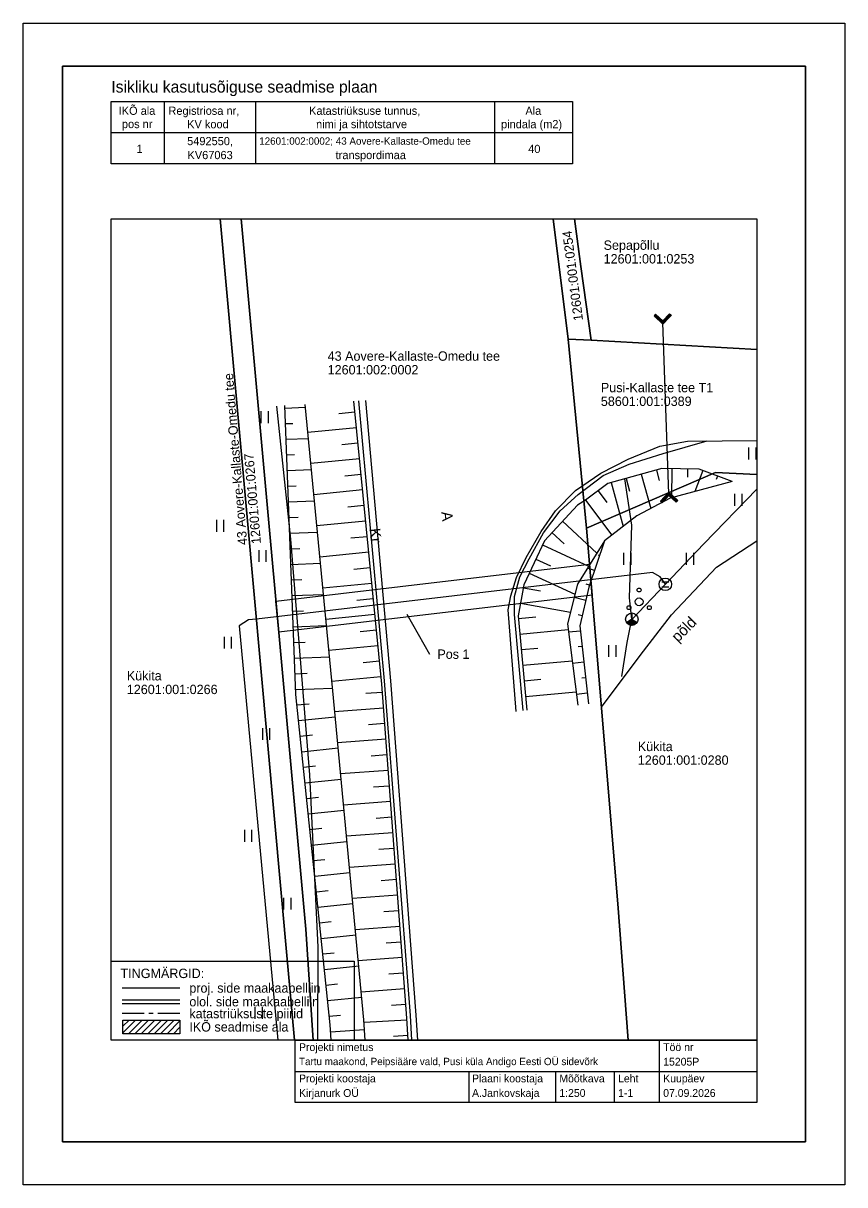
# Model space of a CAD drawing. Extents: x 683366.9 to 683419.4, y 6504541.6 to 6504615.8.
import ezdxf

# ---------------------------------------------------------------- set-up
doc = ezdxf.new("R2010")
doc.units = 0
for name, color, linetype in [('HALJASTUS', 7, 'Continuous'), ('KASUTUSALA', 7, 'Continuous'), ('PIIR', 7, 'Continuous'), ('PR_SIDE', 7, 'Continuous'), ('PUU', 7, 'Continuous'), ('RELJEEF', 7, 'Continuous'), ('SIKAEV', 7, 'Continuous'), ('SITRASS', 7, 'Continuous'), ('TEE', 7, 'Continuous'), ('TRUUP', 7, 'Continuous'), ('VORMISTUS', 7, 'Continuous')]:
    doc.layers.add(name, color=color, linetype=linetype)

msp = doc.modelspace()

# ---------------------------------------------------------------- linework, layer by layer
at = {"layer": 'HALJASTUS'}
for p, q in [((683382.127, 6504591.003), (683382.127, 6504590.242)), ((683382.583, 6504591.003), (683382.583, 6504590.242)), ((683413.292, 6504588.688), (683413.292, 6504587.927)), ((683413.747, 6504588.688), (683413.747, 6504587.927)), ((683412.397, 6504585.715), (683412.397, 6504584.954)), ((683412.852, 6504585.715), (683412.852, 6504584.954)), ((683379.285, 6504584.061), (683379.285, 6504583.3)), ((683379.74, 6504584.061), (683379.74, 6504583.3)), ((683381.983, 6504582.132), (683381.983, 6504581.371)), ((683382.438, 6504582.132), (683382.438, 6504581.371)), ((683405.305, 6504581.949), (683405.305, 6504581.188)), ((683405.76, 6504581.949), (683405.76, 6504581.188)), ((683409.309, 6504581.949), (683409.309, 6504581.188)), ((683409.764, 6504581.949), (683409.764, 6504581.188)), ((683379.767, 6504576.588), (683379.767, 6504575.827)), ((683380.222, 6504576.588), (683380.222, 6504575.827)), ((683404.34, 6504576.059), (683404.34, 6504575.298)), ((683404.795, 6504576.059), (683404.795, 6504575.298)), ((683382.224, 6504570.755), (683382.224, 6504569.993)), ((683382.679, 6504570.755), (683382.679, 6504569.993)), ((683381.068, 6504564.246), (683381.068, 6504563.485)), ((683381.523, 6504564.246), (683381.523, 6504563.485)), ((683383.573, 6504559.907), (683383.573, 6504559.146)), ((683384.028, 6504559.907), (683384.028, 6504559.146)), ((683381.742, 6504552.916), (683381.742, 6504552.155)), ((683382.197, 6504552.916), (683382.197, 6504552.155))]:
    msp.add_line(p, q, dxfattribs=at)
msp.add_lwpolyline([(683403.882, 6504572.085), (683406.35, 6504575.392), (683408.363, 6504577.994), (683411.241, 6504581.038), (683413.81, 6504582.721)], dxfattribs=at)
at = {"layer": 'KASUTUSALA'}
msp.add_lwpolyline([(683403.121, 6504581.232), (683403.287, 6504579.238), (683383.264, 6504576.881), (683383.083, 6504578.873)], close=True, dxfattribs=at)
at = {"layer": 'PIIR'}
for p, q in [((683384.272, 6504550.807), (683379.529, 6504603.307)), ((683379.529, 6504603.307), (683384.272, 6504550.807))]:
    msp.add_line(p, q, dxfattribs=at)
for points in [[(683385.461, 6504550.807), (683384.99, 6504557.89), (683380.863, 6504603.307)], [(683380.863, 6504603.307), (683384.99, 6504557.89), (683385.461, 6504550.807)], [(683400.81, 6504603.307), (683401.76, 6504595.62), (683403.22, 6504595.54), (683402.57, 6504600.25), (683402.154, 6504603.307)], [(683405.591, 6504550.807), (683404.93, 6504559.51), (683402.93, 6504583.52), (683401.76, 6504595.62), (683400.81, 6504603.307)], [(683402.154, 6504603.307), (683402.57, 6504600.25), (683403.22, 6504595.54), (683413.81, 6504594.943)], [(683413.81, 6504594.943), (683403.22, 6504595.54), (683401.76, 6504595.62), (683402.93, 6504583.52), (683411.18, 6504587.08), (683413.81, 6504586.956)], [(683413.81, 6504586.956), (683411.18, 6504587.08), (683402.93, 6504583.52), (683404.93, 6504559.51), (683405.591, 6504550.807)]]:
    msp.add_lwpolyline(points, dxfattribs=at)
at = {"layer": 'PR_SIDE'}
for p, q in [((683405.828, 6504577.696), (683407.97, 6504579.943)), ((683407.737, 6504580.103), (683408.202, 6504580.103)), ((683407.737, 6504579.783), (683408.202, 6504579.783))]:
    msp.add_line(p, q, dxfattribs=at)
for points in [[(683407.97, 6504579.943), (683410.435, 6504582.529), (683413.81, 6504586.014)], [(683407.97, 6504579.943), (683407.639, 6504580.418), (683407.152, 6504580.701), (683381.841, 6504577.72)], [(683381.841, 6504577.72), (683381.328, 6504577.66), (683380.736, 6504577.291), (683383.213, 6504550.807)]]:
    msp.add_lwpolyline(points, dxfattribs=at)
msp.add_circle((683407.97, 6504579.943), 0.4, dxfattribs=at)
at = {"layer": 'PUU'}
for centre, radius in [((683406.294, 6504579.574), 0.125), ((683405.644, 6504578.449), 0.125), ((683406.294, 6504578.824), 0.25), ((683406.944, 6504578.449), 0.125)]:
    msp.add_circle(centre, radius, dxfattribs=at)
at = {"layer": 'RELJEEF'}
for p, q in [((683383.661, 6504591.209), (683384.973, 6504591.259)), ((683388.128, 6504590.944), (683387.096, 6504590.843)), ((683383.7, 6504590.21), (683384.156, 6504590.227)), ((683388.226, 6504589.949), (683385.128, 6504589.644)), ((683383.738, 6504589.21), (683385.164, 6504589.265)), ((683388.324, 6504588.954), (683387.29, 6504588.852)), ((683383.776, 6504588.211), (683384.271, 6504588.23)), ((683388.422, 6504587.959), (683385.319, 6504587.653)), ((683383.815, 6504587.212), (683385.355, 6504587.271)), ((683388.52, 6504586.964), (683387.485, 6504586.862)), ((683405.467, 6504586.709), (683405.687, 6504585.905)), ((683406.432, 6504586.974), (683407.033, 6504584.779)), ((683407.396, 6504587.238), (683407.577, 6504586.577)), ((683408.383, 6504587.326), (683408.363, 6504585.459)), ((683409.383, 6504587.315), (683409.377, 6504586.787)), ((683410.366, 6504587.214), (683409.855, 6504585.863)), ((683411.301, 6504586.86), (683411.216, 6504586.635)), ((683383.853, 6504586.213), (683384.386, 6504586.233)), ((683388.618, 6504585.969), (683385.509, 6504585.662)), ((683403.669, 6504585.916), (683404.23, 6504585.177)), ((683404.503, 6504586.445), (683405.272, 6504583.637)), ((683412.237, 6504586.506), (683412.237, 6504586.506)), ((683383.891, 6504585.213), (683385.546, 6504585.277)), ((683402.873, 6504585.311), (683404.559, 6504583.089)), ((683388.716, 6504584.973), (683387.679, 6504584.871)), ((683383.93, 6504584.214), (683384.5, 6504584.236)), ((683388.815, 6504583.978), (683385.7, 6504583.671)), ((683401.4, 6504583.978), (683403.59, 6504581.939)), ((683383.968, 6504583.215), (683385.737, 6504583.283)), ((683388.913, 6504582.983), (683387.874, 6504582.881)), ((683400.719, 6504583.246), (683401.495, 6504582.523)), ((683384.006, 6504582.216), (683384.615, 6504582.239)), ((683400.114, 6504582.462), (683403.062, 6504581.098)), ((683404.082, 6504582.722), (683404.082, 6504582.722)), ((683389.011, 6504581.988), (683385.891, 6504581.68)), ((683399.694, 6504581.555), (683400.638, 6504581.118)), ((683403.764, 6504581.774), (683403.687, 6504581.799)), ((683384.045, 6504581.216), (683385.928, 6504581.289)), ((683389.109, 6504580.993), (683388.068, 6504580.89)), ((683403.446, 6504580.826), (683402.987, 6504580.979)), ((683384.083, 6504580.217), (683384.73, 6504580.242)), ((683389.207, 6504579.998), (683386.081, 6504579.689)), ((683399.274, 6504580.647), (683402.184, 6504579.301)), ((683403.129, 6504579.877), (683402.899, 6504579.954)), ((683384.121, 6504579.218), (683386.119, 6504579.294)), ((683398.901, 6504579.725), (683399.982, 6504579.528)), ((683389.305, 6504579.002), (683388.262, 6504578.9)), ((683398.722, 6504578.741), (683401.904, 6504578.161)), ((683402.886, 6504578.908), (683402.132, 6504579.087)), ((683384.16, 6504578.219), (683384.845, 6504578.245)), ((683389.403, 6504578.007), (683386.272, 6504577.699)), ((683398.586, 6504577.755), (683399.683, 6504577.855)), ((683402.655, 6504577.935), (683402.401, 6504577.995)), ((683384.198, 6504577.219), (683386.31, 6504577.3)), ((683389.501, 6504577.012), (683388.457, 6504576.909)), ((683398.677, 6504576.759), (683401.769, 6504577.041)), ((683402.539, 6504576.955), (683401.79, 6504576.873)), ((683384.236, 6504576.22), (683384.959, 6504576.248)), ((683389.599, 6504576.017), (683386.463, 6504575.708)), ((683398.767, 6504575.763), (683399.81, 6504575.858)), ((683402.648, 6504575.96), (683402.404, 6504575.934)), ((683384.275, 6504575.221), (683386.501, 6504575.306)), ((683389.698, 6504575.022), (683388.651, 6504574.918)), ((683398.858, 6504574.768), (683402.021, 6504575.056)), ((683402.756, 6504574.966), (683402.042, 6504574.888)), ((683384.313, 6504574.222), (683385.074, 6504574.251)), ((683389.796, 6504574.026), (683386.653, 6504573.717)), ((683384.351, 6504573.222), (683386.692, 6504573.312)), ((683398.949, 6504573.772), (683400.015, 6504573.869)), ((683402.865, 6504573.972), (683402.632, 6504573.947)), ((683389.881, 6504573.03), (683388.835, 6504572.952)), ((683399.039, 6504572.776), (683402.273, 6504573.07)), ((683402.973, 6504572.978), (683402.294, 6504572.904)), ((683384.433, 6504572.226), (683385.213, 6504572.307)), ((683389.956, 6504572.033), (683386.836, 6504571.799)), ((683384.536, 6504571.231), (683386.867, 6504571.472)), ((683390.031, 6504571.036), (683388.998, 6504570.958)), ((683384.638, 6504570.237), (683385.413, 6504570.317)), ((683390.106, 6504570.039), (683387.025, 6504569.807)), ((683384.741, 6504569.242), (683387.056, 6504569.481)), ((683390.181, 6504569.041), (683389.16, 6504568.965)), ((683384.844, 6504568.247), (683385.613, 6504568.327)), ((683390.256, 6504568.044), (683387.214, 6504567.816)), ((683384.947, 6504567.253), (683387.245, 6504567.49)), ((683390.33, 6504567.047), (683389.323, 6504566.971)), ((683385.05, 6504566.258), (683385.813, 6504566.337)), ((683390.405, 6504566.05), (683387.403, 6504565.825)), ((683385.152, 6504565.263), (683387.434, 6504565.499)), ((683385.255, 6504564.268), (683386.013, 6504564.347)), ((683390.48, 6504565.053), (683389.486, 6504564.978)), ((683390.555, 6504564.055), (683387.592, 6504563.833)), ((683385.358, 6504563.274), (683387.623, 6504563.508)), ((683390.63, 6504563.058), (683389.649, 6504562.985)), ((683385.461, 6504562.279), (683386.213, 6504562.357)), ((683385.563, 6504561.284), (683387.812, 6504561.517)), ((683390.704, 6504562.061), (683387.781, 6504561.842)), ((683390.779, 6504561.064), (683389.812, 6504560.991)), ((683385.666, 6504560.29), (683386.413, 6504560.367)), ((683390.854, 6504560.067), (683387.971, 6504559.85)), ((683385.769, 6504559.295), (683388.001, 6504559.526)), ((683390.929, 6504559.069), (683389.974, 6504558.998)), ((683385.872, 6504558.3), (683386.613, 6504558.377)), ((683391.004, 6504558.072), (683388.16, 6504557.859)), ((683385.975, 6504557.305), (683388.19, 6504557.534)), ((683391.079, 6504557.075), (683390.137, 6504557.004)), ((683386.077, 6504556.311), (683386.813, 6504556.387)), ((683386.18, 6504555.316), (683388.379, 6504555.543)), ((683391.153, 6504556.078), (683388.349, 6504555.867)), ((683391.228, 6504555.081), (683390.3, 6504555.011)), ((683386.283, 6504554.321), (683387.013, 6504554.397)), ((683391.303, 6504554.084), (683388.538, 6504553.876)), ((683386.386, 6504553.327), (683388.569, 6504553.552)), ((683391.378, 6504553.086), (683390.463, 6504553.018)), ((683386.488, 6504552.332), (683387.213, 6504552.407)), ((683391.451, 6504552.089), (683388.719, 6504551.92)), ((683386.576, 6504551.336), (683388.749, 6504551.484)), ((683391.513, 6504551.091), (683390.604, 6504551.035))]:
    msp.add_line(p, q, dxfattribs=at)
for points in [[(683386.612, 6504550.807), (683386.546, 6504551.775), (683384.364, 6504572.893), (683383.655, 6504591.362)], [(683388.795, 6504550.807), (683388.707, 6504552.098), (683386.71, 6504573.129), (683384.955, 6504591.445)], [(683391.531, 6504550.807), (683391.445, 6504552.197), (683389.841, 6504573.563), (683388.059, 6504591.641)], [(683412.237, 6504586.506), (683410.12, 6504587.307), (683407.743, 6504587.333), (683404.29, 6504586.387), (683402.87, 6504585.309)], [(683412.237, 6504586.506), (683408.284, 6504585.438), (683406.155, 6504584.316), (683404.082, 6504582.722), (683404.082, 6504582.722)], [(683402.87, 6504585.309), (683402.87, 6504585.309), (683402.349, 6504584.997), (683400.237, 6504582.728), (683398.935, 6504579.914), (683398.571, 6504577.917), (683399.12, 6504571.889)], [(683404.082, 6504582.722), (683402.347, 6504579.959), (683401.721, 6504577.418), (683402.38, 6504572.223)], [(683404.082, 6504582.722), (683403.085, 6504579.748), (683402.503, 6504577.293), (683403.048, 6504572.292)]]:
    msp.add_lwpolyline(points, dxfattribs=at)
at = {"layer": 'SIKAEV'}
for p, q in [((683405.831, 6504577.71), (683405.499, 6504577.49)), ((683405.831, 6504578.11), (683405.831, 6504577.71)), ((683405.831, 6504577.71), (683406.163, 6504577.49))]:
    msp.add_line(p, q, dxfattribs=at)
msp.add_circle((683405.831, 6504577.71), 0.4, dxfattribs=at)
for radius in [0.38, 0.36, 0.34, 0.32, 0.3, 0.28, 0.26, 0.24, 0.22, 0.2, 0.18, 0.16, 0.14, 0.12, 0.1, 0.08, 0.06, 0.04]:
    msp.add_arc((683405.831, 6504577.71), radius, 213.53047, 326.46953, dxfattribs=at)
at = {"layer": 'SITRASS'}
for points in [[(683385.753, 6504550.807), (683385.785, 6504556.743), (683385.248, 6504567.755), (683384.036, 6504582.83), (683383.136, 6504591.331)], [(683405.195, 6504574.053), (683405.532, 6504576.217), (683405.831, 6504577.71), (683405.671, 6504579.075), (683405.836, 6504583.714), (683405.386, 6504586.687)]]:
    msp.add_lwpolyline(points, dxfattribs=at)
at = {"layer": 'TEE'}
msp.add_line((683409.392, 6504589.092), (683413.81, 6504589.126), dxfattribs=at)
for points in [[(683391.772, 6504550.807), (683391.678, 6504552.377), (683390.017, 6504573.76), (683388.371, 6504591.661)], [(683392.145, 6504550.807), (683392.042, 6504552.398), (683390.421, 6504573.765), (683388.835, 6504591.69)], [(683398.434, 6504571.819), (683397.934, 6504578.302), (683398.099, 6504579.204), (683398.449, 6504580.382), (683399.075, 6504581.656), (683400.042, 6504583.318), (683400.952, 6504584.633), (683402.217, 6504585.941), (683403.853, 6504587.052), (683405.602, 6504587.93), (683407.625, 6504588.773), (683409.392, 6504589.092)], [(683398.891, 6504571.866), (683398.331, 6504578.013), (683398.331, 6504579.152), (683398.663, 6504580.415), (683399.274, 6504581.57), (683400.189, 6504583.227), (683401.247, 6504584.642), (683402.407, 6504585.68), (683403.985, 6504586.892), (683405.667, 6504587.617), (683407.83, 6504588.292), (683410.648, 6504589.102)]]:
    msp.add_lwpolyline(points, dxfattribs=at)
at = {"layer": 'TRUUP'}
for p, q in [((683407.343, 6504597.208), (683407.246, 6504597.103)), ((683407.246, 6504597.103), (683407.816, 6504596.573)), ((683407.266, 6504597.125), (683407.289, 6504597.064)), ((683407.285, 6504597.145), (683407.329, 6504597.026)), ((683407.294, 6504597.156), (683407.812, 6504596.674)), ((683407.304, 6504597.166), (683407.37, 6504596.988)), ((683407.323, 6504597.186), (683407.411, 6504596.95)), ((683407.342, 6504597.207), (683407.451, 6504596.912)), ((683407.343, 6504597.208), (683407.808, 6504596.775)), ((683407.382, 6504597.171), (683407.492, 6504596.875)), ((683407.423, 6504597.133), (683407.533, 6504596.837)), ((683407.463, 6504597.096), (683407.573, 6504596.799)), ((683407.504, 6504597.058), (683407.614, 6504596.761)), ((683407.545, 6504597.02), (683407.655, 6504596.723)), ((683407.808, 6504596.775), (683408.242, 6504597.24)), ((683407.812, 6504596.674), (683408.294, 6504597.192)), ((683407.816, 6504596.573), (683408.346, 6504597.143)), ((683408.028, 6504597.011), (683408.083, 6504596.861)), ((683408.047, 6504597.031), (683408.102, 6504596.882)), ((683408.066, 6504597.052), (683408.122, 6504596.902)), ((683408.085, 6504597.072), (683408.141, 6504596.923)), ((683408.104, 6504597.093), (683408.16, 6504596.943)), ((683408.123, 6504597.113), (683408.179, 6504596.964)), ((683408.142, 6504597.134), (683408.198, 6504596.984)), ((683408.161, 6504597.154), (683408.217, 6504597.005)), ((683408.181, 6504597.175), (683408.236, 6504597.025)), ((683408.2, 6504597.195), (683408.255, 6504597.046)), ((683408.219, 6504597.216), (683408.274, 6504597.066)), ((683408.238, 6504597.236), (683408.293, 6504597.087)), ((683408.242, 6504597.24), (683408.346, 6504597.143)), ((683408.274, 6504597.21), (683408.312, 6504597.107)), ((683408.315, 6504597.172), (683408.331, 6504597.128)), ((683407.585, 6504596.982), (683407.695, 6504596.685)), ((683407.626, 6504596.944), (683407.736, 6504596.648)), ((683407.667, 6504596.906), (683407.777, 6504596.61)), ((683407.707, 6504596.869), (683407.817, 6504596.574)), ((683407.748, 6504596.831), (683407.836, 6504596.595)), ((683407.789, 6504596.793), (683407.855, 6504596.615)), ((683408.193, 6504585.728), (683407.812, 6504596.674)), ((683407.818, 6504596.785), (683407.874, 6504596.636)), ((683407.837, 6504596.806), (683407.893, 6504596.656)), ((683407.856, 6504596.826), (683407.912, 6504596.677)), ((683407.876, 6504596.847), (683407.931, 6504596.697)), ((683407.895, 6504596.867), (683407.95, 6504596.718)), ((683407.914, 6504596.888), (683407.969, 6504596.738)), ((683407.933, 6504596.908), (683407.988, 6504596.759)), ((683407.952, 6504596.929), (683408.007, 6504596.779)), ((683407.971, 6504596.949), (683408.026, 6504596.8)), ((683407.99, 6504596.97), (683408.045, 6504596.82)), ((683408.009, 6504596.99), (683408.064, 6504596.841)), ((683408.188, 6504585.828), (683407.665, 6504585.252)), ((683407.771, 6504585.156), (683407.665, 6504585.252)), ((683407.697, 6504585.223), (683407.68, 6504585.267)), ((683407.738, 6504585.186), (683407.698, 6504585.288)), ((683407.774, 6504585.16), (683407.717, 6504585.309)), ((683408.193, 6504585.728), (683407.718, 6504585.204)), ((683407.793, 6504585.181), (683407.736, 6504585.33)), ((683407.812, 6504585.202), (683407.755, 6504585.35)), ((683408.198, 6504585.627), (683407.771, 6504585.156)), ((683407.831, 6504585.222), (683407.774, 6504585.371)), ((683407.85, 6504585.243), (683407.792, 6504585.392)), ((683407.869, 6504585.264), (683407.811, 6504585.413)), ((683407.887, 6504585.285), (683407.83, 6504585.433)), ((683407.906, 6504585.305), (683407.849, 6504585.454)), ((683407.925, 6504585.326), (683407.868, 6504585.475)), ((683407.944, 6504585.347), (683407.887, 6504585.496)), ((683407.963, 6504585.368), (683407.905, 6504585.516)), ((683407.981, 6504585.388), (683407.924, 6504585.537)), ((683408, 6504585.409), (683407.943, 6504585.558)), ((683408.019, 6504585.43), (683407.962, 6504585.579)), ((683408.038, 6504585.45), (683407.981, 6504585.599)), ((683408.057, 6504585.471), (683407.999, 6504585.62)), ((683408.075, 6504585.492), (683408.018, 6504585.641)), ((683408.094, 6504585.513), (683408.037, 6504585.661)), ((683408.113, 6504585.533), (683408.056, 6504585.682)), ((683408.132, 6504585.554), (683408.075, 6504585.703)), ((683408.151, 6504585.575), (683408.093, 6504585.724)), ((683408.169, 6504585.596), (683408.112, 6504585.744)), ((683408.188, 6504585.616), (683408.131, 6504585.765)), ((683408.218, 6504585.609), (683408.15, 6504585.786)), ((683408.259, 6504585.572), (683408.169, 6504585.807)), ((683408.3, 6504585.534), (683408.187, 6504585.827)), ((683408.765, 6504585.305), (683408.188, 6504585.828)), ((683408.717, 6504585.253), (683408.193, 6504585.728)), ((683408.669, 6504585.2), (683408.198, 6504585.627)), ((683408.341, 6504585.497), (683408.228, 6504585.792)), ((683408.382, 6504585.46), (683408.269, 6504585.755)), ((683408.424, 6504585.422), (683408.31, 6504585.718)), ((683408.465, 6504585.385), (683408.351, 6504585.68)), ((683408.506, 6504585.348), (683408.392, 6504585.643)), ((683408.547, 6504585.31), (683408.433, 6504585.606)), ((683408.588, 6504585.273), (683408.475, 6504585.568)), ((683408.629, 6504585.236), (683408.516, 6504585.531)), ((683408.67, 6504585.201), (683408.557, 6504585.494)), ((683408.688, 6504585.221), (683408.598, 6504585.456)), ((683408.707, 6504585.242), (683408.639, 6504585.419)), ((683408.669, 6504585.2), (683408.765, 6504585.305)), ((683408.726, 6504585.263), (683408.68, 6504585.382)), ((683408.745, 6504585.283), (683408.721, 6504585.344))]:
    msp.add_line(p, q, dxfattribs=at)
at = {"layer": 'VORMISTUS'}
for p, q in [((683375.946, 6504610.812), (683375.946, 6504606.812)), ((683381.771, 6504610.812), (683381.771, 6504606.812)), ((683397.046, 6504610.812), (683397.046, 6504606.812)), ((683372.546, 6504608.812), (683402.046, 6504608.812)), ((683391.441, 6504578.028), (683392.901, 6504575.476)), ((683373.256, 6504554.135), (683376.95, 6504554.135)), ((683373.256, 6504553.373), (683376.95, 6504553.373)), ((683374.666, 6504552.5), (683373.255, 6504552.5)), ((683373.256, 6504553.152), (683376.95, 6504553.152)), ((683375.248, 6504552.5), (683374.957, 6504552.5)), ((683376.95, 6504552.5), (683375.539, 6504552.5)), ((683374.119, 6504552.087), (683373.309, 6504551.277)), ((683373.707, 6504552.087), (683373.309, 6504551.689)), ((683374.531, 6504552.087), (683373.657, 6504551.213)), ((683374.943, 6504552.087), (683374.069, 6504551.213)), ((683375.355, 6504552.087), (683374.481, 6504551.213)), ((683375.766, 6504552.087), (683374.893, 6504551.213)), ((683376.178, 6504552.087), (683375.305, 6504551.213)), ((683376.59, 6504552.087), (683375.716, 6504551.213)), ((683376.95, 6504552.035), (683376.128, 6504551.213)), ((683376.95, 6504551.623), (683376.54, 6504551.213)), ((683407.583, 6504550.807), (683407.583, 6504548.807)), ((683384.31, 6504548.807), (683413.81, 6504548.807)), ((683395.403, 6504548.807), (683395.403, 6504546.807)), ((683400.946, 6504548.807), (683400.946, 6504546.807)), ((683404.699, 6504548.807), (683404.699, 6504546.807)), ((683407.583, 6504548.807), (683407.583, 6504546.807))]:
    msp.add_line(p, q, dxfattribs=at)
for points in [[(683366.935, 6504615.807), (683419.435, 6504615.807), (683419.435, 6504541.557), (683366.935, 6504541.557)], [(683369.435, 6504544.307), (683416.935, 6504544.307), (683416.935, 6504613.057), (683369.435, 6504613.057)], [(683369.435, 6504613.057), (683416.935, 6504613.057), (683416.935, 6504544.307), (683369.435, 6504544.307)], [(683372.546, 6504610.812), (683402.046, 6504610.812), (683402.046, 6504606.812), (683372.546, 6504606.812)], [(683413.81, 6504550.807), (683372.56, 6504550.807), (683372.56, 6504603.307), (683413.81, 6504603.307)], [(683372.55, 6504550.8), (683372.55, 6504555.86), (683388.08, 6504555.86), (683388.08, 6504550.8)], [(683373.309, 6504552.087), (683376.95, 6504552.087), (683376.95, 6504551.213), (683373.309, 6504551.213)], [(683384.31, 6504550.807), (683413.81, 6504550.807), (683413.81, 6504546.807), (683384.31, 6504546.807)]]:
    msp.add_lwpolyline(points, close=True, dxfattribs=at)

# ---------------------------------------------------------------- texts
at = {"layer": 'HALJASTUS'}
msp.add_text('põld', height=0.7, rotation=45.0225, dxfattribs=at).set_placement((683408.772, 6504576.194))
at = {"layer": 'PIIR'}
for s, rotation, p in [('12601:001:0254', 97.33176, (683402.713, 6504596.817)), ('43 Aovere-Kallaste-Omedu tee', 94.78015, (683381.256, 6504582.477)), ('12601:001:0267', 94.78015, (683382.128, 6504582.55))]:
    msp.add_text(s, height=0.6, rotation=rotation, dxfattribs=at).set_placement(p)
for s, p in [('Sepapõllu', (683404.024, 6504601.322)), ('12601:001:0253', (683404.024, 6504600.447)), ('43 Aovere-Kallaste-Omedu tee', (683386.389, 6504594.231)), ('12601:002:0002', (683386.389, 6504593.356)), ('Pusi-Kallaste tee T1', (683403.848, 6504592.216)), ('58601:001:0389', (683403.848, 6504591.341)), ('Kükita', (683373.554, 6504573.797)), ('12601:001:0266', (683373.554, 6504572.922)), ('Kükita', (683406.21, 6504569.278)), ('12601:001:0280', (683406.21, 6504568.403))]:
    msp.add_text(s, height=0.6, dxfattribs=at).set_placement(p)
at = {"layer": 'TEE'}
for s, p in [('A', (683393.647, 6504584.561)), ('Kr', (683389.052, 6504583.489))]:
    msp.add_text(s, height=0.7, rotation=276.34328, dxfattribs=at).set_placement(p)
at = {"layer": 'VORMISTUS'}
for s, height, p in [('Isikliku kasutusõiguse seadmise plaan', 0.75, (683372.563, 6504611.374)), ('IKÕ ala', 0.525, (683373.036, 6504609.952)), ('Registriosa nr,', 0.525, (683376.214, 6504609.952)), ('Katastriüksuse tunnus,', 0.525, (683385.204, 6504609.952)), ('Ala', 0.525, (683399.026, 6504609.952)), ('KV kood', 0.525, (683377.411, 6504609.093)), ('nimi ja sihtotstarve', 0.525, (683385.649, 6504609.097)), ('pindala (m2)', 0.525, (683397.469, 6504609.093)), ('pos nr', 0.525, (683373.24, 6504609.101)), ('5492550,', 0.525, (683377.41, 6504608.012)), ('12601:002:0002; 43 Aovere-Kallaste-Omedu tee', 0.47, (683382.014, 6504608.039)), ('1', 0.525, (683374.171, 6504607.512)), ('KV67063', 0.525, (683377.433, 6504607.118)), ('transpordimaa', 0.525, (683386.9, 6504607.118)), ('40', 0.525, (683399.204, 6504607.512)), ('Pos 1', 0.6, (683393.401, 6504575.176)), ('TINGMÄRGID:', 0.6, (683373.15, 6504554.77)), ('proj. side maakaabelliin', 0.6, (683377.55, 6504553.835)), ('olol. side maakaabelliin', 0.6, (683377.55, 6504552.962)), ('katastriüksuste piirid', 0.6, (683377.55, 6504552.2)), ('IKÕ seadmise ala', 0.6, (683377.55, 6504551.35)), ('Projekti nimetus', 0.5, (683384.559, 6504550.103)), ('Töö nr', 0.5, (683407.832, 6504550.103)), ('Tartu maakond, Peipsiääre vald, Pusi küla Andigo Eesti OÜ sidevõrk', 0.47, (683384.559, 6504549.204)), ('15205P', 0.5, (683407.832, 6504549.174)), ('Projekti koostaja', 0.5, (683384.559, 6504548.103)), ('Plaani koostaja', 0.5, (683395.616, 6504548.103)), ('Mõõtkava', 0.5, (683401.195, 6504548.103)), ('Leht', 0.5, (683404.948, 6504548.103)), ('Kuupäev', 0.5, (683407.832, 6504548.103)), ('Kirjanurk OÜ', 0.5, (683384.559, 6504547.174)), ('A.Jankovskaja', 0.5, (683395.616, 6504547.174)), ('1:250', 0.5, (683401.195, 6504547.174)), ('1-1', 0.5, (683404.948, 6504547.174)), ('07.09.2026', 0.5, (683407.832, 6504547.174))]:
    msp.add_text(s, height=height, dxfattribs=at).set_placement(p)

doc.saveas('drawing.dxf')
